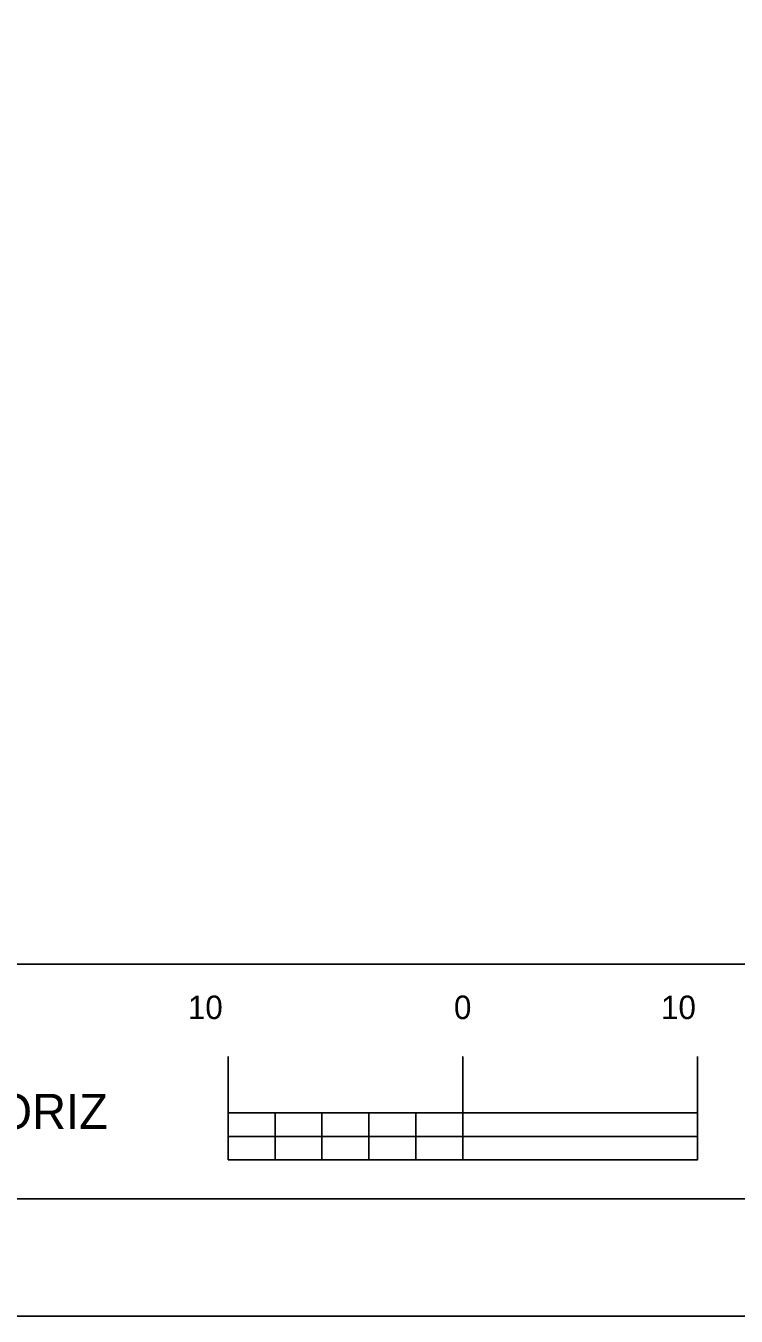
# Model space of a CAD drawing. Extents: x 1797478 to 1805176, y 246529 to 250952.
# Drawn here: x 1802355.4 to 1802385.7, y 250064.4 to 250119.4 of the extents above; entities that cross this region are included whole.
import ezdxf

# ---------------------------------------------------------------- set-up
doc = ezdxf.new("R2010")
doc.units = 0
for name, color, linetype in [('ANNO-SYMB', 7, 'Continuous'), ('Level 62', 7, 'Continuous'), ('SHT-BDR', 7, 'Continuous'), ('SHT-BNDRY', 7, 'Continuous')]:
    doc.layers.add(name, color=color, linetype=linetype)

msp = doc.modelspace()

# ---------------------------------------------------------------- linework, layer by layer
at = {"layer": 'ANNO-SYMB'}
for p, q in [((1802364.069, 250071.086), (1802364.069, 250075.486)), ((1802374.069, 250071.086), (1802374.069, 250075.486)), ((1802374.069, 250071.086), (1802374.069, 250075.486)), ((1802374.069, 250071.086), (1802374.069, 250075.486)), ((1802384.069, 250071.086), (1802384.069, 250075.486)), ((1802384.069, 250073.086), (1802364.069, 250073.086)), ((1802366.069, 250072.086), (1802366.069, 250073.086)), ((1802366.069, 250072.086), (1802366.069, 250073.086)), ((1802374.069, 250072.086), (1802374.069, 250073.086)), ((1802374.069, 250072.086), (1802374.069, 250073.086)), ((1802374.069, 250072.086), (1802374.069, 250073.086)), ((1802374.069, 250072.086), (1802370.069, 250072.086)), ((1802384.069, 250071.086), (1802384.069, 250072.086)), ((1802384.069, 250071.086), (1802384.069, 250072.086)), ((1802384.069, 250071.086), (1802384.069, 250072.086)), ((1802384.069, 250071.086), (1802364.069, 250071.086))]:
    msp.add_line(p, q, dxfattribs=at)
for points in [[(1802364.069, 250073.086), (1802366.069, 250073.086), (1802366.069, 250072.086), (1802364.069, 250072.086)], [(1802368.069, 250073.086), (1802370.069, 250073.086), (1802370.069, 250072.086), (1802368.069, 250072.086)], [(1802372.069, 250073.086), (1802374.069, 250073.086), (1802374.069, 250072.086), (1802372.069, 250072.086)], [(1802366.069, 250072.086), (1802368.069, 250072.086), (1802368.069, 250071.086), (1802366.069, 250071.086)], [(1802370.069, 250072.086), (1802372.069, 250072.086), (1802372.069, 250071.086), (1802370.069, 250071.086)], [(1802374.069, 250072.086), (1802384.069, 250072.086), (1802384.069, 250071.086), (1802374.069, 250071.086)]]:
    msp.add_lwpolyline(points, close=True, dxfattribs=at)
at = {"layer": 'Level 62'}
msp.add_lwpolyline([(1802116.005, 250064.422), (1802456.005, 250064.422), (1802456.005, 250284.422), (1802116.005, 250284.422)], close=True, dxfattribs=at)
at = {"layer": 'SHT-BDR'}
msp.add_lwpolyline([(1802141.002, 250079.432), (1802441.002, 250079.432), (1802441.002, 250269.432), (1802141.002, 250269.432)], close=True, dxfattribs=at)
at = {"layer": 'SHT-BNDRY'}
msp.add_lwpolyline([(1802128.505, 250069.422), (1802451.005, 250069.422), (1802451.005, 250279.422), (1802128.505, 250279.422)], close=True, dxfattribs=at)

# ---------------------------------------------------------------- texts
at = {"layer": 'ANNO-SYMB'}
for s, height, p in [(' 10', 0.9991, (1802361.984, 250077.085)), ('0', 1, (1802373.695, 250077.086)), ('0', 1, (1802373.695, 250077.086)), ('0', 1, (1802373.695, 250077.086)), (' 10', 0.9991, (1802382.15, 250077.086)), ('HORIZ', 1.4994, (1802352.707, 250072.394))]:
    msp.add_text(s, height=height, rotation=0.0572, dxfattribs=at).set_placement(p)

doc.saveas('drawing.dxf')
